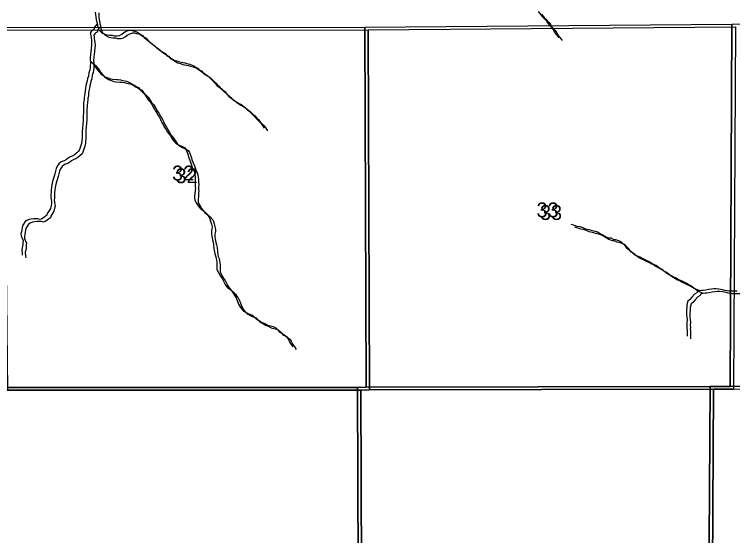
# Model space of a CAD drawing. Extents: x -21.1 to 50.3, y 0 to 22.1.
# Drawn here: x 45.19 to 47.215, y 19.298 to 20.767 of the extents above; entities that cross this region are included whole.
import ezdxf

# ---------------------------------------------------------------- set-up
doc = ezdxf.new("R2010")
doc.units = 0
for name, color, linetype in [('GM_X_Minor_River', 7, 'Continuous'), ('GM_X_Section', 7, 'Continuous'), ('GM_X_Section_Text', 7, 'Continuous')]:
    doc.layers.add(name, color=color, linetype=linetype)

msp = doc.modelspace()

# ---------------------------------------------------------------- linework, layer by layer
at = {"layer": 'GM_X_Minor_River'}
for points in [[(45.4185, 20.7731), (45.4189, 20.7663), (45.4197, 20.7594), (45.4213, 20.7522), (45.4221, 20.7477), (45.4236, 20.7431), (45.4248, 20.7359), (45.4264, 20.7299), (45.4279, 20.7245), (45.4371, 20.7155), (45.447, 20.7102), (45.4531, 20.7091), (45.4585, 20.7088), (45.4661, 20.708), (45.4718, 20.7066), (45.4809, 20.7062), (45.4866, 20.7078), (45.4931, 20.7112), (45.4988, 20.7158), (45.5041, 20.7185), (45.5086, 20.7204), (45.5143, 20.7227)], [(45.4281, 20.7717), (45.4281, 20.7656), (45.4286, 20.7588), (45.4294, 20.7519), (45.4309, 20.7447), (45.4317, 20.7402), (45.4333, 20.7356), (45.4344, 20.7284), (45.436, 20.7224), (45.4376, 20.717), (45.4467, 20.708), (45.4567, 20.7027), (45.4628, 20.7016), (45.4681, 20.7013), (45.4757, 20.7005), (45.4814, 20.6991), (45.4906, 20.6987), (45.4963, 20.7003), (45.5027, 20.7037), (45.5084, 20.7083), (45.5137, 20.711), (45.5183, 20.7129), (45.524, 20.7152)], [(46.667, 20.7751), (46.6743, 20.7653), (46.6789, 20.7615), (46.6843, 20.7558), (46.6889, 20.7517), (46.692, 20.7456), (46.6962, 20.7392), (46.7046, 20.7297), (46.71, 20.7229), (46.7119, 20.7176), (46.718, 20.7104), (46.7226, 20.7051), (46.7257, 20.7006)], [(46.6767, 20.7676), (46.684, 20.7578), (46.6886, 20.754), (46.6939, 20.7483), (46.6985, 20.7442), (46.7016, 20.7381), (46.7058, 20.7317), (46.7142, 20.7222), (46.7196, 20.7154), (46.7215, 20.7101), (46.7277, 20.7029), (46.7323, 20.6976), (46.7353, 20.6931)], [(45.4241, 20.7401), (45.4161, 20.7313), (45.4146, 20.7249), (45.4089, 20.7214), (45.4047, 20.7164), (45.4055, 20.7115), (45.4056, 20.7069), (45.4067, 20.7005), (45.4075, 20.6948), (45.4083, 20.6887), (45.4076, 20.6788), (45.4069, 20.6739), (45.4065, 20.6693), (45.4058, 20.6621), (45.4047, 20.6549), (45.404, 20.6435), (45.4044, 20.6382), (45.4049, 20.6294), (45.4045, 20.6222), (45.4042, 20.6165), (45.4027, 20.6112), (45.4004, 20.6024), (45.399, 20.5933), (45.3967, 20.5865), (45.3956, 20.58), (45.3934, 20.5732), (45.3923, 20.5667), (45.3908, 20.5591), (45.3901, 20.5522), (45.3893, 20.5443), (45.3882, 20.5382), (45.3875, 20.5329), (45.3868, 20.5279), (45.3857, 20.5165), (45.385, 20.5047), (45.3851, 20.4914), (45.3848, 20.4785), (45.3841, 20.4679), (45.383, 20.4565), (45.3823, 20.4477), (45.382, 20.436), (45.382, 20.4234), (45.3817, 20.4181), (45.381, 20.412), (45.3795, 20.4033), (45.3757, 20.3919), (45.3739, 20.3865), (45.3716, 20.3816), (45.3667, 20.3766), (45.3595, 20.3716), (45.3538, 20.3678), (45.3481, 20.3655), (45.342, 20.3617), (45.3375, 20.3582), (45.331, 20.3548), (45.3219, 20.3513), (45.3155, 20.3459), (45.3109, 20.3394), (45.3079, 20.3326), (45.3064, 20.3254), (45.3046, 20.3178), (45.3023, 20.3109), (45.3009, 20.3052), (45.2986, 20.2995), (45.2967, 20.2919), (45.2956, 20.2869), (45.2949, 20.279), (45.2938, 20.2729), (45.2938, 20.2679), (45.2935, 20.2565), (45.2932, 20.2516), (45.294, 20.2459), (45.2948, 20.2398), (45.2955, 20.2345), (45.2941, 20.2284), (45.2918, 20.2201), (45.2892, 20.2151), (45.2831, 20.2056), (45.2824, 20.201), (45.2775, 20.1972), (45.2725, 20.1937), (45.268, 20.1911), (45.2627, 20.1887), (45.257, 20.1906), (45.252, 20.191), (45.2448, 20.1909), (45.2379, 20.1897), (45.2318, 20.1893), (45.2254, 20.1866), (45.2205, 20.1836), (45.2163, 20.1763), (45.2133, 20.171), (45.2126, 20.1664), (45.2111, 20.1611), (45.2103, 20.1543), (45.2089, 20.1486), (45.2093, 20.1432), (45.2116, 20.1383), (45.215, 20.1296), (45.2143, 20.125), (45.214, 20.1182)], [(45.4338, 20.7326), (45.4257, 20.7238), (45.4242, 20.7173), (45.4185, 20.7139), (45.4144, 20.7089), (45.4152, 20.704), (45.4152, 20.6994), (45.4164, 20.693), (45.4172, 20.6873), (45.418, 20.6812), (45.4173, 20.6713), (45.4165, 20.6664), (45.4162, 20.6618), (45.4155, 20.6546), (45.4143, 20.6474), (45.4137, 20.636), (45.4141, 20.6307), (45.4145, 20.6219), (45.4142, 20.6147), (45.4138, 20.609), (45.4123, 20.6037), (45.4101, 20.5949), (45.4086, 20.5858), (45.4064, 20.579), (45.4053, 20.5725), (45.403, 20.5657), (45.4019, 20.5592), (45.4004, 20.5516), (45.3997, 20.5447), (45.399, 20.5368), (45.3979, 20.5307), (45.3971, 20.5254), (45.3964, 20.5204), (45.3953, 20.509), (45.3946, 20.4972), (45.3947, 20.4839), (45.3944, 20.471), (45.3937, 20.4604), (45.3926, 20.449), (45.3919, 20.4402), (45.3916, 20.4284), (45.3917, 20.4159), (45.3913, 20.4106), (45.3906, 20.4045), (45.3891, 20.3958), (45.3854, 20.3843), (45.3835, 20.379), (45.3812, 20.3741), (45.3763, 20.3691), (45.3691, 20.3641), (45.3634, 20.3603), (45.3577, 20.358), (45.3517, 20.3542), (45.3471, 20.3507), (45.3407, 20.3473), (45.3315, 20.3438), (45.3251, 20.3384), (45.3206, 20.3319), (45.3176, 20.3251), (45.3161, 20.3179), (45.3142, 20.3103), (45.312, 20.3034), (45.3105, 20.2977), (45.3082, 20.292), (45.3064, 20.2844), (45.3053, 20.2794), (45.3045, 20.2715), (45.3034, 20.2654), (45.3035, 20.2604), (45.3032, 20.249), (45.3028, 20.2441), (45.3036, 20.2384), (45.3044, 20.2323), (45.3052, 20.227), (45.3037, 20.2209), (45.3015, 20.2126), (45.2988, 20.2076), (45.2928, 20.1981), (45.292, 20.1935), (45.2871, 20.1897), (45.2822, 20.1862), (45.2776, 20.1836), (45.2723, 20.1812), (45.2666, 20.1831), (45.2616, 20.1835), (45.2544, 20.1834), (45.2476, 20.1822), (45.2415, 20.1818), (45.235, 20.1791), (45.2301, 20.1761), (45.2259, 20.1688), (45.2229, 20.1635), (45.2222, 20.1589), (45.2207, 20.1536), (45.22, 20.1468), (45.2185, 20.1411), (45.2189, 20.1357), (45.2212, 20.1308), (45.2247, 20.1221), (45.224, 20.1175), (45.2236, 20.1107)], [(45.5143, 20.7227), (45.5197, 20.7228), (45.525, 20.7209), (45.5303, 20.7194), (45.5353, 20.7175), (45.5441, 20.7123), (45.5521, 20.7074), (45.5567, 20.7021), (45.5667, 20.6934), (45.5743, 20.6881), (45.58, 20.6832), (45.5873, 20.6779), (45.5915, 20.6734), (45.5969, 20.6693), (45.6018, 20.6651), (45.6152, 20.6568), (45.6198, 20.6512), (45.6293, 20.6455), (45.6408, 20.6384), (45.6488, 20.6357), (45.6561, 20.6331), (45.6606, 20.632), (45.6713, 20.6302), (45.6766, 20.6287), (45.685, 20.6272), (45.6915, 20.6238), (45.6965, 20.6219), (45.7026, 20.6178), (45.7079, 20.6152), (45.7129, 20.6103), (45.719, 20.6054), (45.7297, 20.5986), (45.7343, 20.5948), (45.742, 20.5876), (45.7492, 20.5805), (45.7569, 20.5725), (45.7626, 20.5661), (45.7733, 20.5586), (45.7787, 20.5517), (45.791, 20.5408), (45.7952, 20.5359), (45.8024, 20.5306), (45.8074, 20.5272), (45.8131, 20.5227), (45.8196, 20.5189), (45.8257, 20.5148), (45.8315, 20.5118), (45.838, 20.5065), (45.8452, 20.5008), (45.8521, 20.4944), (45.8582, 20.4887), (45.8651, 20.4816), (45.8697, 20.4778), (45.8732, 20.4729), (45.8797, 20.4661), (45.8839, 20.4612), (45.8877, 20.4566), (45.8916, 20.4509), (45.8943, 20.446)], [(45.524, 20.7152), (45.5293, 20.7153), (45.5346, 20.7134), (45.54, 20.7119), (45.5449, 20.71), (45.5537, 20.7048), (45.5617, 20.6999), (45.5663, 20.6946), (45.5763, 20.6859), (45.5839, 20.6806), (45.5897, 20.6757), (45.5969, 20.6704), (45.6011, 20.6659), (45.6065, 20.6618), (45.6115, 20.6576), (45.6248, 20.6493), (45.6294, 20.6437), (45.639, 20.638), (45.6504, 20.6309), (45.6585, 20.6282), (45.6657, 20.6256), (45.6703, 20.6245), (45.6809, 20.6227), (45.6863, 20.6212), (45.6947, 20.6197), (45.7012, 20.6163), (45.7061, 20.6144), (45.7122, 20.6103), (45.7176, 20.6077), (45.7225, 20.6028), (45.7287, 20.5979), (45.7394, 20.5911), (45.7439, 20.5873), (45.7516, 20.5801), (45.7589, 20.573), (45.7665, 20.565), (45.7723, 20.5586), (45.783, 20.5511), (45.7883, 20.5442), (45.8006, 20.5333), (45.8048, 20.5284), (45.8121, 20.5231), (45.817, 20.5197), (45.8228, 20.5152), (45.8293, 20.5114), (45.8354, 20.5073), (45.8411, 20.5043), (45.8476, 20.499), (45.8549, 20.4933), (45.8618, 20.4869), (45.8679, 20.4812), (45.8748, 20.4741), (45.8794, 20.4703), (45.8828, 20.4654), (45.8893, 20.4586), (45.8935, 20.4537), (45.8974, 20.4491), (45.9012, 20.4434), (45.9039, 20.4385)], [(45.4046, 20.6348), (45.4098, 20.6302), (45.4159, 20.6227), (45.4205, 20.6174), (45.424, 20.6121), (45.4301, 20.6045), (45.4351, 20.5985), (45.4466, 20.5913), (45.4542, 20.5879), (45.4614, 20.5857), (45.4672, 20.5846), (45.4782, 20.5835), (45.4835, 20.5832), (45.49, 20.5824), (45.4965, 20.5809), (45.5068, 20.5787), (45.5129, 20.5765), (45.519, 20.5735), (45.5243, 20.5697), (45.5289, 20.5678), (45.5335, 20.5641), (45.54, 20.5607), (45.5461, 20.5539), (45.558, 20.5414), (45.5611, 20.5369), (45.5649, 20.5308), (45.5676, 20.5263), (45.5729, 20.521), (45.5787, 20.5126), (45.5818, 20.5054), (45.5852, 20.5001), (45.5887, 20.4948), (45.5918, 20.4899), (45.5937, 20.4854), (45.5983, 20.4782), (45.6022, 20.4706), (45.606, 20.4623), (45.6095, 20.457), (45.6141, 20.4486), (45.6172, 20.4433), (45.6222, 20.4354), (45.6256, 20.4308), (45.6302, 20.4244), (45.6337, 20.4191), (45.6375, 20.4134), (45.641, 20.4089), (45.6455, 20.4044), (45.6517, 20.4006), (45.6581, 20.398), (45.6662, 20.3942), (45.6707, 20.3908), (45.675, 20.3855), (45.6769, 20.3806), (45.6792, 20.373), (45.6823, 20.3632), (45.685, 20.356), (45.6881, 20.3476), (45.692, 20.3362), (45.6958, 20.3287), (45.6978, 20.3222), (45.6993, 20.3146), (45.6998, 20.3089), (45.7002, 20.3017), (45.7006, 20.2949), (45.6999, 20.2877), (45.7003, 20.2808), (45.7007, 20.2763), (45.7003, 20.2713), (45.6996, 20.2611), (45.6985, 20.2546), (45.6986, 20.2497), (45.6994, 20.244), (45.7051, 20.233), (45.7082, 20.2277), (45.7143, 20.2209), (45.7201, 20.216), (45.7273, 20.2088), (45.7331, 20.2043), (45.74, 20.196), (45.7419, 20.1914), (45.7438, 20.1842), (45.7458, 20.1762), (45.7477, 20.1686), (45.7474, 20.1629), (45.7463, 20.1557), (45.746, 20.1477), (45.7471, 20.1417), (45.7491, 20.1322), (45.7507, 20.125), (45.7522, 20.1181), (45.753, 20.1064), (45.7546, 20.0976), (45.7558, 20.0927), (45.7577, 20.0867), (45.7593, 20.0802), (45.7612, 20.0688), (45.7614, 20.0483), (45.7664, 20.0381), (45.7717, 20.0297), (45.7752, 20.0244), (45.7787, 20.0172)], [(45.4142, 20.6273), (45.4194, 20.6227), (45.4256, 20.6152), (45.4302, 20.6099), (45.4336, 20.6046), (45.4398, 20.597), (45.4447, 20.591), (45.4562, 20.5838), (45.4638, 20.5804), (45.4711, 20.5782), (45.4768, 20.5771), (45.4878, 20.576), (45.4932, 20.5757), (45.4996, 20.5749), (45.5061, 20.5734), (45.5164, 20.5712), (45.5225, 20.569), (45.5286, 20.566), (45.534, 20.5622), (45.5385, 20.5603), (45.5431, 20.5566), (45.5496, 20.5532), (45.5558, 20.5464), (45.5676, 20.5339), (45.5707, 20.5294), (45.5745, 20.5233), (45.5772, 20.5188), (45.5826, 20.5135), (45.5883, 20.5051), (45.5914, 20.4979), (45.5949, 20.4926), (45.5983, 20.4873), (45.6014, 20.4824), (45.6033, 20.4779), (45.6079, 20.4707), (45.6118, 20.4631), (45.6157, 20.4548), (45.6191, 20.4495), (45.6237, 20.4411), (45.6268, 20.4358), (45.6318, 20.4279), (45.6352, 20.4233), (45.6398, 20.4169), (45.6433, 20.4116), (45.6471, 20.4059), (45.6506, 20.4014), (45.6552, 20.3969), (45.6613, 20.3931), (45.6678, 20.3905), (45.6758, 20.3867), (45.6804, 20.3833), (45.6846, 20.378), (45.6865, 20.3731), (45.6889, 20.3655), (45.692, 20.3557), (45.6947, 20.3485), (45.6978, 20.3401), (45.7016, 20.3287), (45.7055, 20.3212), (45.7074, 20.3147), (45.709, 20.3071), (45.7094, 20.3014), (45.7098, 20.2942), (45.7102, 20.2874), (45.7095, 20.2802), (45.7099, 20.2733), (45.7103, 20.2688), (45.71, 20.2638), (45.7093, 20.2536), (45.7082, 20.2471), (45.7082, 20.2422), (45.709, 20.2365), (45.7148, 20.2255), (45.7178, 20.2202), (45.724, 20.2134), (45.7297, 20.2085), (45.737, 20.2013), (45.7427, 20.1968), (45.7496, 20.1885), (45.7515, 20.1839), (45.7535, 20.1767), (45.7554, 20.1687), (45.7574, 20.1611), (45.757, 20.1554), (45.7559, 20.1482), (45.7556, 20.1402), (45.7568, 20.1342), (45.7587, 20.1247), (45.7603, 20.1175), (45.7619, 20.1106), (45.7627, 20.0989), (45.7643, 20.0901), (45.7654, 20.0852), (45.7674, 20.0792), (45.7689, 20.0727), (45.7709, 20.0613), (45.771, 20.0408), (45.776, 20.0306), (45.7814, 20.0222), (45.7848, 20.0169), (45.7883, 20.0097)], [(47.1233, 19.9883), (47.1118, 19.9931), (47.1065, 19.9957), (47.1019, 19.9984), (47.0973, 20.0018), (47.0924, 20.0052), (47.0863, 20.0086), (47.079, 20.0123), (47.0714, 20.0164), (47.0622, 20.0198), (47.0542, 20.0247), (47.0485, 20.027), (47.0427, 20.0307), (47.0366, 20.0345), (47.0317, 20.0375), (47.0271, 20.0405), (47.0206, 20.0443), (47.0145, 20.0496), (47.0087, 20.0529), (47.0038, 20.0563), (46.9988, 20.0594), (46.9935, 20.062), (46.9877, 20.0654), (46.9828, 20.0684), (46.9782, 20.0706), (46.9709, 20.0744), (46.9629, 20.0781), (46.9545, 20.0827), (46.9473, 20.086), (46.9408, 20.0898), (46.935, 20.0939), (46.9293, 20.0973), (46.9243, 20.1015), (46.9182, 20.1071), (46.9132, 20.1136), (46.9075, 20.12), (46.9025, 20.1249), (46.8945, 20.1287), (46.8857, 20.1317), (46.8792, 20.1331), (46.8728, 20.1361), (46.8667, 20.1369), (46.8571, 20.1406), (46.8495, 20.1451), (46.8396, 20.1504), (46.8342, 20.153), (46.8289, 20.1549), (46.8243, 20.156), (46.8193, 20.1575), (46.8148, 20.1586), (46.8098, 20.1601), (46.8014, 20.1623), (46.7942, 20.1653), (46.7854, 20.168), (46.7774, 20.1694), (46.7728, 20.1713), (46.7667, 20.1732), (46.7606, 20.1747)], [(47.133, 19.9808), (47.1215, 19.9856), (47.1161, 19.9882), (47.1116, 19.9909), (47.107, 19.9943), (47.102, 19.9977), (47.0959, 20.0011), (47.0886, 20.0048), (47.081, 20.0089), (47.0718, 20.0123), (47.0638, 20.0172), (47.0581, 20.0195), (47.0524, 20.0232), (47.0463, 20.027), (47.0413, 20.03), (47.0367, 20.033), (47.0302, 20.0368), (47.0241, 20.0421), (47.0184, 20.0454), (47.0134, 20.0488), (47.0084, 20.0519), (47.0031, 20.0545), (46.9974, 20.0579), (46.9924, 20.0609), (46.9878, 20.0631), (46.9806, 20.0669), (46.9725, 20.0706), (46.9641, 20.0752), (46.9569, 20.0785), (46.9504, 20.0823), (46.9447, 20.0864), (46.9389, 20.0898), (46.934, 20.094), (46.9278, 20.0996), (46.9229, 20.1061), (46.9171, 20.1125), (46.9121, 20.1174), (46.9041, 20.1212), (46.8954, 20.1242), (46.8889, 20.1256), (46.8824, 20.1286), (46.8763, 20.1294), (46.8668, 20.1331), (46.8591, 20.1376), (46.8492, 20.1429), (46.8438, 20.1455), (46.8385, 20.1474), (46.8339, 20.1485), (46.829, 20.15), (46.8244, 20.1511), (46.8194, 20.1526), (46.8111, 20.1548), (46.8038, 20.1578), (46.795, 20.1605), (46.787, 20.1619), (46.7825, 20.1638), (46.7764, 20.1657), (46.7703, 20.1672)], [(45.214, 20.1182), (45.2136, 20.1136), (45.2114, 20.1045), (45.2126, 20.0946), (45.2126, 20.0886)], [(45.2236, 20.1107), (45.2233, 20.1061), (45.221, 20.097), (45.2222, 20.0871), (45.2223, 20.0811)], [(45.7787, 20.0172), (45.7829, 20.0093), (45.786, 20.0044), (45.7917, 19.9976), (45.7975, 19.993), (45.8043, 19.9862), (45.8074, 19.9817), (45.8105, 19.9764), (45.8155, 19.9681), (45.8186, 19.9605), (45.8221, 19.9506), (45.8247, 19.9457), (45.8278, 19.9412), (45.8328, 19.9351), (45.8366, 19.9306), (45.8443, 19.9272), (45.8515, 19.9234), (45.8622, 19.9193), (45.8718, 19.9091), (45.8836, 19.9024), (45.8886, 19.899), (45.8966, 19.8963), (45.905, 19.8915), (45.9202, 19.8874), (45.9271, 19.884), (45.9328, 19.8779), (45.9375, 19.8719), (45.9439, 19.8685), (45.9497, 19.8647), (45.9573, 19.8595), (45.9612, 19.8538), (45.9662, 19.8443), (45.9692, 19.8394), (45.9754, 19.8303)], [(45.7883, 20.0097), (45.7925, 20.0018), (45.7956, 19.9969), (45.8014, 19.9901), (45.8071, 19.9855), (45.814, 19.9787), (45.8171, 19.9742), (45.8201, 19.9689), (45.8251, 19.9606), (45.8282, 19.953), (45.8317, 19.9431), (45.8344, 19.9382), (45.8375, 19.9337), (45.8424, 19.9276), (45.8463, 19.9231), (45.8539, 19.9197), (45.8612, 19.9159), (45.8718, 19.9118), (45.8814, 19.9016), (45.8932, 19.8948), (45.8982, 19.8915), (45.9062, 19.8888), (45.9146, 19.884), (45.9299, 19.8799), (45.9367, 19.8765), (45.9425, 19.8704), (45.9471, 19.8644), (45.9536, 19.861), (45.9593, 19.8572), (45.967, 19.852), (45.9708, 19.8463), (45.9758, 19.8368), (45.9789, 19.8319), (45.985, 19.8228)], [(47.2284, 19.9869), (47.2051, 19.9868), (47.2002, 19.9879), (47.1933, 19.989), (47.1872, 19.9905), (47.1815, 19.992), (47.1769, 19.9931), (47.1689, 19.9938), (47.1625, 19.9938), (47.1556, 19.993), (47.1476, 19.9918), (47.14, 19.9902), (47.1328, 19.9894), (47.1282, 19.9887), (47.1218, 19.9882), (47.1172, 19.9882), (47.1146, 19.9829), (47.1077, 19.979), (47.1002, 19.9699), (47.0937, 19.963), (47.0888, 19.9592), (47.0862, 19.9482), (47.0859, 19.9402), (47.0851, 19.9352), (47.0852, 19.9299), (47.0856, 19.9208), (47.086, 19.9147), (47.0868, 19.9067), (47.0865, 19.8995), (47.0865, 19.8919), (47.0862, 19.8874), (47.0866, 19.8828), (47.087, 19.8764), (47.087, 19.8718), (47.0874, 19.8669), (47.0871, 19.86)], [(47.238, 19.9794), (47.2148, 19.9793), (47.2098, 19.9804), (47.203, 19.9815), (47.1969, 19.983), (47.1911, 19.9845), (47.1866, 19.9856), (47.1786, 19.9863), (47.1721, 19.9863), (47.1653, 19.9855), (47.1573, 19.9843), (47.1497, 19.9827), (47.1424, 19.9819), (47.1379, 19.9812), (47.1314, 19.9807), (47.1268, 19.9807), (47.1242, 19.9754), (47.1174, 19.9715), (47.1098, 19.9624), (47.1034, 19.9555), (47.0984, 19.9517), (47.0958, 19.9407), (47.0955, 19.9327), (47.0948, 19.9277), (47.0948, 19.9224), (47.0952, 19.9133), (47.0957, 19.9072), (47.0965, 19.8992), (47.0961, 19.892), (47.0962, 19.8844), (47.0958, 19.8799), (47.0962, 19.8753), (47.0966, 19.8689), (47.0967, 19.8643), (47.0971, 19.8594), (47.0967, 19.8525)]]:
    msp.add_lwpolyline(points, dxfattribs=at)
at = {"layer": 'GM_X_Section'}
for points in [[(46.1781, 20.7313), (47.2135, 20.7399), (47.2087, 19.7187), (47.1518, 19.7186), (46.1819, 19.7163)], [(47.2135, 20.7399), (48.2077, 20.7436), (48.2146, 19.7248), (48.1627, 19.7232), (47.2087, 19.7187)], [(45.1509, 20.7296), (46.1781, 20.7313), (46.1819, 19.7163), (46.1577, 19.7161), (45.1623, 19.7162)], [(45.1605, 20.7221), (46.1877, 20.7238), (46.1915, 19.7088), (46.1673, 19.7086), (45.1719, 19.7087)], [(46.1877, 20.7238), (47.2232, 20.7324), (47.2183, 19.7112), (47.1615, 19.7111), (46.1915, 19.7088)], [(45.1623, 19.7162), (46.1577, 19.7161), (46.1612, 18.6969), (45.1314, 18.7262), (45.1286, 19.7159)], [(45.1719, 19.7087), (46.1673, 19.7086), (46.1708, 18.6894), (45.1411, 18.7187), (45.1382, 19.7084)], [(46.1577, 19.7161), (46.1819, 19.7163), (47.1518, 19.7186), (47.1458, 18.7035), (46.1612, 18.6969)], [(46.1673, 19.7086), (46.1915, 19.7088), (47.1615, 19.7111), (47.1555, 18.696), (46.1708, 18.6894)], [(48.1627, 19.7232), (48.1626, 18.7259), (47.1458, 18.7035), (47.1518, 19.7186), (47.2087, 19.7187)], [(48.1723, 19.7157), (48.1722, 18.7184), (47.1555, 18.696), (47.1615, 19.7111), (47.2183, 19.7112)]]:
    msp.add_lwpolyline(points, close=True, dxfattribs=at)

# ---------------------------------------------------------------- texts
at = {"layer": 'GM_X_Section_Text'}
for s, p in [('32', (45.6351, 20.299)), ('32', (45.6447, 20.2915)), ('33', (46.6626, 20.1953)), ('33', (46.6722, 20.1878))]:
    msp.add_text(s, height=0.04186, rotation=0, dxfattribs=at).set_placement(p)

doc.saveas('drawing.dxf')
